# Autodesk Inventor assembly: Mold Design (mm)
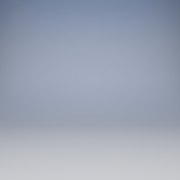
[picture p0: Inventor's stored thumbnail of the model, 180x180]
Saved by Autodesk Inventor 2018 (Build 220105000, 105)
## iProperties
Shininess: 64.0
Length Units: 11269
Angle Units: 11279
Time Units: 11290
Mass Units: 11283
Length Display Precision: 3
Angle Display Precision: 2
Compacted: True
Created: 2002-07
Part Number: Mold Design (mm)
Document SubType Name: Assembly
Material: Ogólny
Density: 0.0
Volumn: 0.0
Area: 0.0
PropertySet Name: Model Information
Control State: 0
Master: False
Checked Out: False
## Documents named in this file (1)
- C:\Users\Joffi\Desktop\Templates.Base\Metric.Base\Mold Design (mm).iam
